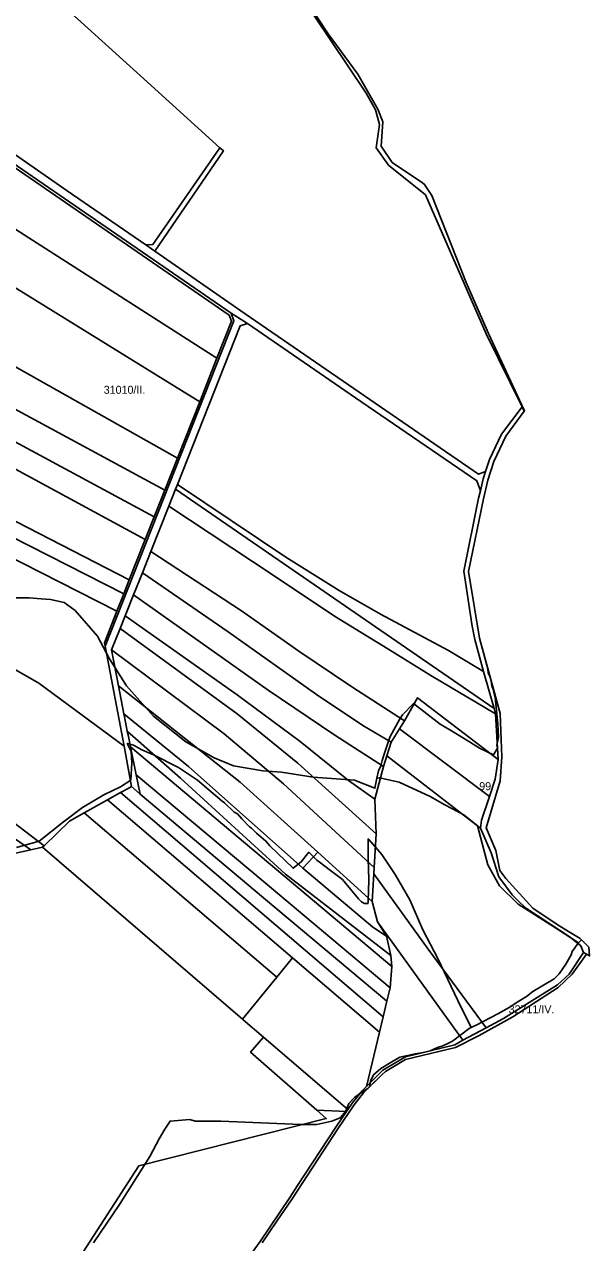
# Model space of a CAD drawing. Extents: x -541351 to -537540, y -1162694 to -1159725.
# Drawn here: x -537985 to -537632, y -1162097 to -1161336 of the extents above; entities that cross this region are included whole.
import ezdxf

# ---------------------------------------------------------------- set-up
doc = ezdxf.new("R2010")
doc.units = 0
for name, color, linetype in [('95560013', 7, 'Continuous'), ('95590013', 7, 'Continuous'), ('95600013', 7, 'Continuous'), ('95610013', 7, 'Continuous'), ('95620013', 7, 'Continuous'), ('95630013', 7, 'Continuous'), ('95640013', 7, 'Continuous'), ('95660013', 7, 'Continuous')]:
    doc.layers.add(name, color=color, linetype=linetype)

msp = doc.modelspace()

# ---------------------------------------------------------------- linework, layer by layer
at = {"layer": '95560013'}
for points in [[(-537991.61, -1161206.61), (-537962.32, -1161184.95), (-537917.43, -1161151.64), (-537878.78, -1161215.29), (-537826.79, -1161296.05), (-537771.59, -1161378.63), (-537765.56, -1161389.07), (-537763.17, -1161398.15), (-537765.32, -1161412.85), (-537757.44, -1161423.63), (-537734.41, -1161442.14), (-537710.31, -1161497.52), (-537696.57, -1161528.99), (-537674.08, -1161574.59), (-537686.87, -1161591.71), (-537694.5, -1161607.51), (-537696.89, -1161615.11), (-537701.32, -1161616.63), (-537847.19, -1161516.44), (-537903.61, -1161477.42), (-537860.67, -1161414.77), (-537862.95, -1161412.71), (-537910.48, -1161369.63), (-537986.93, -1161300.34)], [(-538017.3, -1161723.84), (-537976.1, -1161747.28), (-537922.75, -1161786.65), (-537918.1, -1161811.88), (-537920.21, -1161813.06), (-537924.94, -1161815.7), (-537933.13, -1161820.26), (-537947.8, -1161828.43), (-537956.93, -1161833.52), (-537972.84, -1161848.95), (-538003.7, -1161825.37)]]:
    msp.add_lwpolyline(points, dxfattribs=at)
for points in [[(-537862.95, -1161412.71), (-537904.74, -1161473.13), (-537909.29, -1161473.5), (-537958.26, -1161439.63), (-538014.16, -1161400.98), (-537997.12, -1161376.05), (-538023.45, -1161358.02), (-537986.93, -1161300.34), (-537910.48, -1161369.63)], [(-538105.85, -1161390.01), (-538102.7, -1161355.1), (-538068.79, -1161374.81), (-538039.72, -1161391.26), (-538023.13, -1161403.11), (-537857.1, -1161517.37), (-537855.67, -1161521.18), (-537864.8, -1161544.29)], [(-538105.85, -1161390.01), (-537864.8, -1161544.29), (-537875.53, -1161571.44), (-538109.19, -1161427.11)], [(-537860.67, -1161414.77), (-537903.61, -1161477.42), (-537909.29, -1161473.5), (-537904.74, -1161473.13), (-537862.95, -1161412.71)], [(-537875.53, -1161571.44), (-537889.5, -1161606.78), (-538114.02, -1161480.19), (-538113.05, -1161469.94), (-538110.81, -1161445.05), (-538109.19, -1161427.11)], [(-537889.5, -1161606.78), (-537897.41, -1161626.8), (-538116.68, -1161508.18), (-538114.02, -1161480.19)], [(-538116.68, -1161508.18), (-537897.41, -1161626.8), (-537903.96, -1161643.38), (-538118.52, -1161527.74), (-538118.09, -1161523)], [(-537903.96, -1161643.38), (-537909.56, -1161657.55), (-538121.06, -1161543.08), (-538120.2, -1161539.46), (-538118.52, -1161527.74)], [(-537909.56, -1161657.55), (-537919.51, -1161682.72), (-538130.97, -1161574.04), (-538129.59, -1161571.04), (-538123.99, -1161555.42), (-538121.06, -1161543.08)], [(-537919.51, -1161682.72), (-537923, -1161691.55), (-538029.12, -1161637.46), (-538135.24, -1161583.36), (-538130.97, -1161574.04)], [(-538029.12, -1161637.46), (-537923, -1161691.55), (-537927.26, -1161702.34), (-538033.98, -1161648.19), (-538140.69, -1161594.04), (-538136.53, -1161586.17), (-538135.24, -1161583.36)], [(-538171.84, -1161653.01), (-538140.69, -1161594.04), (-538033.98, -1161648.19), (-537927.26, -1161702.34), (-537935.04, -1161722.01), (-537934.61, -1161724.27), (-537922.75, -1161786.65), (-537976.1, -1161747.28), (-538017.3, -1161723.84), (-538107.66, -1161682.18)], [(-537889.44, -1161623.23), (-537821.78, -1161668.5), (-537788.35, -1161689.41), (-537762.49, -1161704.25), (-537720.04, -1161726.92), (-537698.17, -1161739.95), (-537691.59, -1161763.18), (-537890.56, -1161626.05)], [(-537837.81, -1162096.24), (-537857.15, -1162122.84), (-537876.73, -1162149.18), (-537890.98, -1162165.98), (-537913.23, -1162197.28), (-537922.33, -1162211.34), (-537935.55, -1162238.66), (-537996.43, -1162244.72), (-538003.43, -1162189.61), (-537980.73, -1162152.69), (-537959.1, -1162119.55), (-537913.59, -1162048.98), (-537796.39, -1162019.36), (-537802.31, -1162014.18), (-537783.76, -1162015.03), (-537790.37, -1162024.85), (-537814.41, -1162061.25), (-537819.11, -1162068.63)]]:
    msp.add_lwpolyline(points, close=True, dxfattribs=at)
at = {"layer": '95590013'}
for points in [[(-538091.99, -1161778.95), (-538074.06, -1161787.96), (-538055.69, -1161796.19), (-538037.67, -1161805.21), (-538020.32, -1161814.34), (-538003.7, -1161825.37), (-537972.84, -1161848.95), (-537973.7, -1161849.78), (-537981.13, -1161851.43), (-538007.24, -1161833.28), (-538024.07, -1161822.21), (-538041.78, -1161812.94), (-538059.87, -1161804.11), (-538096.14, -1161786.78), (-538132.5, -1161770.02), (-538150.71, -1161762.54), (-538201.11, -1161745.28), (-538199.78, -1161734.53), (-538146.62, -1161754.58), (-538127.98, -1161761.85), (-538109.61, -1161770.43)], [(-538026.82, -1161826.8), (-538044.18, -1161817.14), (-538062.2, -1161808.5), (-538098.22, -1161791.29), (-538135.28, -1161774.83), (-538201.84, -1161750.78), (-538201.11, -1161745.28), (-538150.71, -1161762.54), (-538132.5, -1161770.02), (-538096.14, -1161786.78), (-538059.87, -1161804.11), (-538041.78, -1161812.94), (-538024.07, -1161822.21), (-538007.24, -1161833.28), (-537981.13, -1161851.43), (-537992.56, -1161853.98), (-538010.17, -1161838.34)]]:
    msp.add_lwpolyline(points, close=True, dxfattribs=at)
at = {"layer": '95600013'}
for points in [[(-537791.3, -1161705.39), (-537829.69, -1161679.86), (-537894.84, -1161636.79), (-537890.56, -1161626.05), (-537691.59, -1161763.18), (-537690.68, -1161766.41), (-537730.97, -1161742.54), (-537758.05, -1161725.77)], [(-537849.4, -1161702.1), (-537906.05, -1161664.94), (-537894.84, -1161636.79), (-537829.69, -1161679.86), (-537791.3, -1161705.39), (-537758.05, -1161725.77), (-537730.97, -1161742.54), (-537690.68, -1161766.41), (-537688.95, -1161795.06), (-537739.44, -1161756.52), (-537747.56, -1161770.78), (-537780.43, -1161749.61), (-537813.5, -1161727.27)], [(-537780.43, -1161749.61), (-537747.56, -1161770.78), (-537750.68, -1161775.88), (-537755.79, -1161784.25), (-537773.52, -1161773.76), (-537802.6, -1161754.38), (-537857.67, -1161715.17), (-537911.36, -1161678.27), (-537906.05, -1161664.94), (-537849.4, -1161702.1), (-537813.5, -1161727.27)], [(-537857.67, -1161715.17), (-537802.6, -1161754.38), (-537773.52, -1161773.76), (-537755.79, -1161784.25), (-537758.48, -1161792.69), (-537760.6, -1161799.37), (-537791.01, -1161779.72), (-537832.83, -1161751.77), (-537916.91, -1161692.2), (-537911.36, -1161678.27)], [(-537916.91, -1161692.2), (-537832.83, -1161751.77), (-537791.01, -1161779.72), (-537760.6, -1161799.37), (-537765.99, -1161819.86), (-537782.63, -1161808.05), (-537812.67, -1161783.81), (-537852.02, -1161754.53), (-537922.07, -1161705.16)], [(-537852.02, -1161754.53), (-537812.67, -1161783.81), (-537782.63, -1161808.05), (-537765.99, -1161819.86), (-537765.19, -1161841.44), (-537814.14, -1161797.39), (-537852.09, -1161766.39), (-537925.23, -1161713.1), (-537922.07, -1161705.16)], [(-537765.19, -1161841.44), (-537766.56, -1161862.48), (-537823.19, -1161810.16), (-537860.22, -1161779.07), (-537930.6, -1161726.57), (-537925.23, -1161713.1), (-537852.09, -1161766.39), (-537814.14, -1161797.39)], [(-537801.8, -1161852.95), (-537850.3, -1161809.08), (-537926.26, -1161749.03), (-537930.6, -1161726.57), (-537860.22, -1161779.07), (-537823.19, -1161810.16), (-537766.56, -1161862.48), (-537766.78, -1161866.44), (-537767.71, -1161883.69)], [(-537850.3, -1161809.08), (-537801.8, -1161852.95), (-537811.01, -1161862.99), (-537882.54, -1161799.41), (-537922.87, -1161766.53), (-537926.26, -1161749.03)], [(-537817.45, -1161918.97), (-537763.12, -1161965.33), (-537771.22, -1161999.31), (-537773.95, -1162002.03), (-537780.15, -1162009.66), (-537782.94, -1162013.81), (-537835.7, -1161968.44), (-537848.3, -1161957.61), (-537848.8, -1161957.17), (-537827.34, -1161931.02)]]:
    msp.add_lwpolyline(points, close=True, dxfattribs=at)
at = {"layer": '95610013'}
msp.add_lwpolyline([(-537758.48, -1161792.69), (-537700.05, -1161838.01), (-537693.46, -1161853.35), (-537688.55, -1161868.27), (-537680.33, -1161879.54), (-537675.39, -1161884.28), (-537671.25, -1161888.12), (-537643.95, -1161906.13), (-537637.28, -1161911.4), (-537635.7, -1161915.56), (-537644.66, -1161929.12), (-537651.82, -1161935.75), (-537685.72, -1161956.91), (-537696.51, -1161962.69), (-537732.73, -1161913.5), (-537766.78, -1161866.44), (-537766.56, -1161862.48), (-537765.19, -1161841.44), (-537765.99, -1161819.86), (-537760.6, -1161799.37)], close=True, dxfattribs=at)
at = {"layer": '95620013'}
for points in [[(-537702.37, -1161620.84), (-537699.93, -1161627.14), (-537701.21, -1161631.77), (-537710.48, -1161677.27), (-537705.21, -1161711.74), (-537703.67, -1161719.97), (-537698.17, -1161739.95), (-537720.04, -1161726.92), (-537762.49, -1161704.25), (-537788.35, -1161689.41), (-537821.78, -1161668.5), (-537889.44, -1161623.23), (-537850.3, -1161524.02), (-537845.61, -1161522.58), (-537778.16, -1161568.95)], [(-537688.95, -1161795.06), (-537690.81, -1161807.3), (-537694.46, -1161818.19), (-537750.68, -1161775.88), (-537747.56, -1161770.78), (-537739.44, -1161756.52)], [(-537920.77, -1161777.39), (-537922.53, -1161768.3), (-537922.87, -1161766.53), (-537882.54, -1161799.41), (-537811.01, -1161862.99), (-537767.34, -1161899.85), (-537758.71, -1161905.42), (-537755.97, -1161917.48), (-537821.84, -1161866.67), (-537887.61, -1161806.63)], [(-537887.61, -1161806.63), (-537821.84, -1161866.67), (-537755.97, -1161917.48), (-537755.43, -1161924.33), (-537918.82, -1161787.06), (-537920.34, -1161779.64), (-537920.77, -1161777.39)], [(-537699.36, -1161832.85), (-537700.05, -1161838.01), (-537758.48, -1161792.69), (-537755.79, -1161784.25), (-537750.68, -1161775.88), (-537694.46, -1161818.19)], [(-537755.43, -1161924.33), (-537756.52, -1161937.62), (-537835.88, -1161871.12), (-537915.24, -1161804.63), (-537918.82, -1161787.06)], [(-537915.24, -1161804.63), (-537835.88, -1161871.12), (-537756.52, -1161937.62), (-537758.52, -1161946), (-537835.64, -1161881.39), (-537912.77, -1161816.77)], [(-537760.86, -1161955.85), (-537763.12, -1161965.33), (-537817.45, -1161918.97), (-537933.13, -1161820.26), (-537924.94, -1161815.7)], [(-537924.94, -1161815.7), (-537920.21, -1161813.06), (-537918.1, -1161811.88), (-537912.77, -1161816.77), (-537835.64, -1161881.39), (-537758.52, -1161946), (-537760.86, -1161955.85)], [(-537827.34, -1161931.02), (-537947.8, -1161828.43), (-537933.13, -1161820.26), (-537817.45, -1161918.97)], [(-537947.8, -1161828.43), (-537827.34, -1161931.02), (-537848.8, -1161957.17), (-537973.7, -1161849.78), (-537972.84, -1161848.95), (-537956.93, -1161833.52)], [(-537767.71, -1161883.69), (-537764.33, -1161896.38), (-537758.71, -1161905.42), (-537767.34, -1161899.85), (-537811.01, -1161862.99), (-537801.8, -1161852.95)], [(-537767.71, -1161883.69), (-537766.78, -1161866.44), (-537732.73, -1161913.5), (-537696.51, -1161962.69), (-537710.98, -1161970.44), (-537764.33, -1161896.38)], [(-537763.12, -1161965.33), (-537760.86, -1161955.85), (-537758.52, -1161946), (-537756.52, -1161937.62), (-537755.43, -1161924.33), (-537755.97, -1161917.48), (-537758.71, -1161905.42), (-537764.33, -1161896.38), (-537710.98, -1161970.44), (-537716.17, -1161973.22), (-537746.83, -1161980.83), (-537761.1, -1161989.21), (-537771.22, -1161999.31)], [(-537843.78, -1161977.81), (-537835.7, -1161968.44), (-537782.94, -1162013.81), (-537783.76, -1162015.03), (-537802.31, -1162014.18)]]:
    msp.add_lwpolyline(points, close=True, dxfattribs=at)
msp.add_lwpolyline([(-537992.56, -1161853.98), (-537981.13, -1161851.43), (-537973.7, -1161849.78), (-537848.8, -1161957.17), (-537848.3, -1161957.61), (-537835.7, -1161968.44), (-537843.78, -1161977.81), (-537802.31, -1162014.18), (-537796.39, -1162019.36), (-537913.59, -1162048.98), (-537959.1, -1162119.55)], dxfattribs=at)
at = {"layer": '95630013'}
msp.add_lwpolyline([(-537857.1, -1161517.37), (-538023.13, -1161403.11), (-538039.72, -1161391.26), (-538022.41, -1161401.67), (-537855.9, -1161516.2), (-537854.21, -1161520.85), (-537934.61, -1161724.27), (-537935.04, -1161722.01), (-537927.26, -1161702.34), (-537923, -1161691.55), (-537919.51, -1161682.72), (-537909.56, -1161657.55), (-537903.96, -1161643.38), (-537897.41, -1161626.8), (-537889.5, -1161606.78), (-537875.53, -1161571.44), (-537864.8, -1161544.29), (-537855.67, -1161521.18)], close=True, dxfattribs=at)
at = {"layer": '95640013'}
for points in [[(-537825.35, -1161295.54), (-537795.27, -1161341.6), (-537776.77, -1161366.86), (-537764.17, -1161388.68), (-537761.11, -1161396.65), (-537762.15, -1161411.84), (-537755.16, -1161421.95), (-537736.27, -1161434.72), (-537734.93, -1161435.64), (-537730.5, -1161442.66), (-537709.02, -1161496.84), (-537695, -1161528.73), (-537674.2, -1161573.51), (-537672.5, -1161577.12), (-537672.71, -1161577.37), (-537674.08, -1161574.59), (-537696.57, -1161528.99), (-537710.31, -1161497.52), (-537734.41, -1161442.14), (-537757.44, -1161423.63), (-537765.32, -1161412.85), (-537763.17, -1161398.15), (-537765.56, -1161389.07), (-537771.59, -1161378.63), (-537826.79, -1161296.05)], [(-537857.15, -1162122.84), (-537837.81, -1162096.24), (-537819.11, -1162068.63), (-537814.41, -1162061.25), (-537790.37, -1162024.85), (-537783.76, -1162015.03), (-537782.94, -1162013.81), (-537780.15, -1162009.66), (-537773.95, -1162002.03), (-537771.22, -1161999.31), (-537761.1, -1161989.21), (-537746.83, -1161980.83), (-537716.17, -1161973.22), (-537710.98, -1161970.44), (-537696.51, -1161962.69), (-537685.72, -1161956.91), (-537651.82, -1161935.75), (-537644.66, -1161929.12), (-537635.7, -1161915.56), (-537633.76, -1161916.66), (-537642.83, -1161929.21), (-537651.4, -1161937.54), (-537679.87, -1161955.73), (-537700.91, -1161967.52), (-537715.69, -1161974.89), (-537746.83, -1161982.53), (-537759.37, -1161989.91), (-537761.46, -1161991.89), (-537773.2, -1162003.37), (-537778.94, -1162010.74), (-537789.26, -1162025.76), (-537817.83, -1162069.52), (-537827.3, -1162083.56), (-537836.59, -1162097.02)]]:
    msp.add_lwpolyline(points, dxfattribs=at)
for points in [[(-538039.72, -1161391.26), (-538068.79, -1161374.81), (-538102.7, -1161355.1), (-538098.33, -1161347.51), (-538089.39, -1161352.67), (-538074.35, -1161361.36), (-538072.11, -1161362.66), (-538063.88, -1161366.6), (-538039.54, -1161383.43), (-538014.16, -1161400.98), (-537958.26, -1161439.63), (-537909.29, -1161473.5), (-537903.61, -1161477.42), (-537847.19, -1161516.44), (-537701.32, -1161616.63), (-537696.89, -1161615.11), (-537698.29, -1161619.58), (-537699.93, -1161627.14), (-537702.37, -1161620.84), (-537778.16, -1161568.95), (-537845.61, -1161522.58), (-537855.9, -1161516.2), (-538022.41, -1161401.67)], [(-537920.77, -1161777.39), (-537920.34, -1161779.64), (-537918.82, -1161787.06), (-537915.24, -1161804.63), (-537912.77, -1161816.77), (-537918.1, -1161811.88), (-537922.75, -1161786.65), (-537934.61, -1161724.27), (-537854.21, -1161520.85), (-537855.9, -1161516.2), (-537845.61, -1161522.58), (-537850.3, -1161524.02), (-537889.44, -1161623.23), (-537890.56, -1161626.05), (-537894.84, -1161636.79), (-537906.05, -1161664.94), (-537911.36, -1161678.27), (-537916.91, -1161692.2), (-537922.07, -1161705.16), (-537925.23, -1161713.1), (-537930.6, -1161726.57), (-537926.26, -1161749.03), (-537922.87, -1161766.53), (-537922.53, -1161768.3)], [(-537631.82, -1161917.75), (-537633.76, -1161916.66), (-537635.7, -1161915.56), (-537637.28, -1161911.4), (-537643.95, -1161906.13), (-537671.25, -1161888.12), (-537675.39, -1161884.28), (-537680.33, -1161879.54), (-537688.55, -1161868.27), (-537693.46, -1161853.35), (-537700.05, -1161838.01), (-537699.36, -1161832.85), (-537694.46, -1161818.19), (-537690.81, -1161807.3), (-537688.95, -1161795.06), (-537690.68, -1161766.41), (-537691.59, -1161763.18), (-537698.17, -1161739.95), (-537703.67, -1161719.97), (-537705.21, -1161711.74), (-537710.48, -1161677.27), (-537701.21, -1161631.77), (-537699.93, -1161627.14), (-537698.29, -1161619.58), (-537696.89, -1161615.11), (-537694.5, -1161607.51), (-537686.87, -1161591.71), (-537674.08, -1161574.59), (-537672.71, -1161577.37), (-537672.5, -1161577.12), (-537672.7, -1161577.39), (-537684.16, -1161592.93), (-537691.63, -1161608.81), (-537695.49, -1161620.49), (-537698.16, -1161632.19), (-537707.43, -1161677.5), (-537700.63, -1161719.2), (-537687.64, -1161766.24), (-537686.73, -1161793.4), (-537687.81, -1161808.36), (-537696.57, -1161837.73), (-537690.36, -1161851.82), (-537687.85, -1161864.33), (-537684.3, -1161869.41), (-537667.35, -1161887.98), (-537652.11, -1161898.02), (-537645.1, -1161902.57), (-537637.73, -1161906.76), (-537632.39, -1161912.23)]]:
    msp.add_lwpolyline(points, close=True, dxfattribs=at)
at = {"layer": '95660013'}
for points in [[(-537825.35, -1161295.54), (-537795.27, -1161341.6), (-537776.77, -1161366.86), (-537764.17, -1161388.68), (-537761.11, -1161396.65), (-537762.15, -1161411.84), (-537755.16, -1161421.95), (-537736.27, -1161434.72), (-537734.93, -1161435.64), (-537730.5, -1161442.66), (-537709.02, -1161496.84), (-537695, -1161528.73), (-537674.2, -1161573.51), (-537672.5, -1161577.12), (-537672.7, -1161577.39), (-537684.16, -1161592.93), (-537691.63, -1161608.81), (-537695.49, -1161620.49), (-537698.16, -1161632.19), (-537707.43, -1161677.5), (-537700.63, -1161719.2), (-537695.36, -1161738.27), (-537695.31, -1161741), (-537693.87, -1161744), (-537693.31, -1161746), (-537692.87, -1161749), (-537692.21, -1161751.22), (-537691.69, -1161753), (-537690.81, -1161756), (-537689.12, -1161773), (-537688.81, -1161781), (-537689.81, -1161786), (-537689.5, -1161788), (-537691.81, -1161792), (-537700.62, -1161788), (-537706.81, -1161784), (-537718.19, -1161777), (-537725.31, -1161773), (-537741.87, -1161760), (-537748.81, -1161767), (-537750.62, -1161770), (-537756.62, -1161781), (-537757.31, -1161783), (-537760.69, -1161793), (-537761.44, -1161795.67), (-537762.37, -1161799), (-537763.81, -1161802), (-537764.75, -1161806.7), (-537766, -1161813), (-537778.87, -1161808), (-537804.62, -1161806), (-537824.31, -1161803), (-537836.12, -1161802), (-537854.31, -1161799), (-537866.5, -1161794), (-537884.12, -1161784), (-537904.37, -1161768), (-537921.37, -1161749), (-537931.87, -1161732), (-537939.37, -1161718), (-537953.31, -1161702), (-537960.19, -1161697), (-537968.69, -1161695), (-537974.66, -1161694.56), (-537982.12, -1161694), (-537997.5, -1161694)], [(-537997.5, -1161694), (-537982.12, -1161694), (-537974.66, -1161694.56), (-537968.69, -1161695), (-537960.19, -1161697), (-537953.31, -1161702), (-537939.37, -1161718), (-537931.87, -1161732), (-537921.37, -1161749), (-537904.37, -1161768), (-537884.12, -1161784), (-537866.5, -1161794), (-537854.31, -1161799), (-537836.12, -1161802), (-537824.31, -1161803), (-537804.62, -1161806), (-537778.87, -1161808), (-537766, -1161813), (-537764.75, -1161806.7), (-537763.2, -1161806.4), (-537750.9, -1161809.2), (-537731.5, -1161818.1), (-537722.4, -1161823.3), (-537710.4, -1161829.6), (-537701.9, -1161836.5), (-537695.4, -1161860.8), (-537688.2, -1161874), (-537676.4, -1161885.4), (-537652.6, -1161900.6), (-537638.74, -1161909.58), (-537639.12, -1161910), (-537641.1, -1161912.78), (-537642.69, -1161915), (-537643.31, -1161917), (-537646.62, -1161923), (-537650.87, -1161929), (-537654, -1161932), (-537667.31, -1161940), (-537671.37, -1161943), (-537676, -1161946), (-537682.19, -1161950), (-537689.12, -1161954), (-537702.81, -1161961), (-537705.79, -1161962.38), (-537714.3, -1161945.7), (-537726.6, -1161919.3), (-537736.1, -1161901.4), (-537744.3, -1161882.8), (-537753.35, -1161866.86), (-537761.6, -1161854.4), (-537769.77, -1161844.97), (-537770.16, -1161844.52), (-537770.31, -1161857), (-537769.87, -1161870), (-537770.05, -1161877.22), (-537770.19, -1161883), (-537770.27, -1161883.89), (-537770.37, -1161885), (-537772.62, -1161885), (-537774.31, -1161884), (-537776.37, -1161882), (-537786.37, -1161870), (-537792.94, -1161865), (-537798.19, -1161861), (-537800.05, -1161859.67), (-537802.37, -1161858), (-537807.37, -1161853), (-537812.12, -1161859), (-537817.12, -1161863), (-537831.62, -1161849), (-537834.12, -1161846), (-537840, -1161841), (-537843.12, -1161838), (-537844.31, -1161837), (-537849.19, -1161832), (-537852, -1161829), (-537854, -1161828), (-537860, -1161822), (-537861.5, -1161821), (-537869.87, -1161814), (-537877, -1161808), (-537888.87, -1161800), (-537904.31, -1161792), (-537911.62, -1161789), (-537916.81, -1161786), (-537920.81, -1161785), (-537918.31, -1161790), (-537917.87, -1161797), (-537918.62, -1161808), (-537925.12, -1161812), (-537935.37, -1161817), (-537948.81, -1161825), (-537960.69, -1161834), (-537975.87, -1161846), (-537990.12, -1161850)], [(-537990.12, -1161850), (-537975.87, -1161846), (-537960.69, -1161834), (-537948.81, -1161825), (-537935.37, -1161817), (-537925.12, -1161812), (-537918.62, -1161808), (-537917.87, -1161797), (-537918.31, -1161790), (-537920.81, -1161785), (-537916.81, -1161786), (-537911.62, -1161789), (-537904.31, -1161792), (-537888.87, -1161800), (-537877, -1161808), (-537869.87, -1161814), (-537861.5, -1161821), (-537860, -1161822), (-537854, -1161828), (-537852, -1161829), (-537849.19, -1161832), (-537844.31, -1161837), (-537843.12, -1161838), (-537840, -1161841), (-537834.12, -1161846), (-537831.62, -1161849), (-537817.12, -1161863), (-537812.12, -1161859), (-537807.37, -1161853), (-537802.37, -1161858), (-537800.05, -1161859.67), (-537798.19, -1161861), (-537792.94, -1161865), (-537786.37, -1161870), (-537776.37, -1161882), (-537774.31, -1161884), (-537772.62, -1161885), (-537770.37, -1161885), (-537770.27, -1161883.89), (-537770.19, -1161883), (-537770.05, -1161877.22), (-537769.87, -1161870), (-537770.31, -1161857), (-537770.16, -1161844.52), (-537769.77, -1161844.97), (-537761.6, -1161854.4), (-537753.35, -1161866.86), (-537744.3, -1161882.8), (-537736.1, -1161901.4), (-537726.6, -1161919.3), (-537714.3, -1161945.7), (-537705.79, -1161962.38), (-537707.12, -1161963), (-537717.5, -1161971), (-537719.62, -1161972), (-537723.62, -1161974), (-537726.87, -1161975), (-537731.5, -1161977), (-537735.62, -1161978), (-537740.87, -1161979), (-537750.37, -1161981), (-537755.37, -1161984), (-537762.37, -1161988), (-537766.87, -1161992), (-537768.87, -1161996), (-537769.32, -1161999.58), (-537770.37, -1162000.6), (-537774.37, -1162003), (-537778.62, -1162006), (-537782.31, -1162010), (-537784.37, -1162015), (-537786.21, -1162017.22), (-537787.69, -1162019), (-537792.87, -1162021), (-537802.31, -1162023), (-537812.31, -1162023), (-537862.31, -1162021), (-537878.31, -1162021), (-537881.69, -1162020), (-537894, -1162021), (-537897.37, -1162026), (-537900.81, -1162032), (-537906.62, -1162043), (-537925.62, -1162073), (-537941.87, -1162097)], [(-537941.87, -1162097), (-537925.62, -1162073), (-537906.62, -1162043), (-537900.81, -1162032), (-537897.37, -1162026), (-537894, -1162021), (-537881.69, -1162020), (-537878.31, -1162021), (-537862.31, -1162021), (-537812.31, -1162023), (-537802.31, -1162023), (-537792.87, -1162021), (-537787.69, -1162019), (-537786.21, -1162017.22), (-537784.37, -1162015), (-537782.31, -1162010), (-537778.62, -1162006), (-537774.37, -1162003), (-537770.37, -1162000.6), (-537773.2, -1162003.37), (-537778.94, -1162010.74), (-537789.26, -1162025.76), (-537817.83, -1162069.52), (-537827.3, -1162083.56), (-537836.59, -1162097.02)]]:
    msp.add_lwpolyline(points, dxfattribs=at)
for points in [[(-537637.73, -1161906.76), (-537636.92, -1161907.59), (-537638.74, -1161909.58), (-537652.6, -1161900.6), (-537676.4, -1161885.4), (-537688.2, -1161874), (-537695.4, -1161860.8), (-537701.9, -1161836.5), (-537710.4, -1161829.6), (-537722.4, -1161823.3), (-537731.5, -1161818.1), (-537750.9, -1161809.2), (-537763.2, -1161806.4), (-537764.75, -1161806.7), (-537763.81, -1161802), (-537762.37, -1161799), (-537761.44, -1161795.67), (-537760.69, -1161793), (-537757.31, -1161783), (-537756.62, -1161781), (-537750.62, -1161770), (-537748.81, -1161767), (-537741.87, -1161760), (-537725.31, -1161773), (-537718.19, -1161777), (-537706.81, -1161784), (-537700.62, -1161788), (-537691.81, -1161792), (-537689.5, -1161788), (-537689.81, -1161786), (-537688.81, -1161781), (-537689.12, -1161773), (-537690.81, -1161756), (-537691.69, -1161753), (-537692.21, -1161751.22), (-537692.87, -1161749), (-537693.31, -1161746), (-537693.87, -1161744), (-537695.31, -1161741), (-537695.36, -1161738.27), (-537687.64, -1161766.24), (-537686.73, -1161793.4), (-537687.81, -1161808.36), (-537696.57, -1161837.73), (-537690.36, -1161851.82), (-537687.85, -1161864.33), (-537684.3, -1161869.41), (-537667.35, -1161887.98), (-537652.11, -1161898.02), (-537645.1, -1161902.57)], [(-537632.39, -1161912.23), (-537631.82, -1161917.75), (-537633.76, -1161916.66), (-537642.83, -1161929.21), (-537651.4, -1161937.54), (-537679.87, -1161955.73), (-537700.91, -1161967.52), (-537715.69, -1161974.89), (-537746.83, -1161982.53), (-537759.37, -1161989.91), (-537761.46, -1161991.89), (-537769.32, -1161999.58), (-537768.87, -1161996), (-537766.87, -1161992), (-537762.37, -1161988), (-537755.37, -1161984), (-537750.37, -1161981), (-537740.87, -1161979), (-537735.62, -1161978), (-537731.5, -1161977), (-537726.87, -1161975), (-537723.62, -1161974), (-537719.62, -1161972), (-537717.5, -1161971), (-537707.12, -1161963), (-537705.79, -1161962.38), (-537702.81, -1161961), (-537689.12, -1161954), (-537682.19, -1161950), (-537676, -1161946), (-537671.37, -1161943), (-537667.31, -1161940), (-537654, -1161932), (-537650.87, -1161929), (-537646.62, -1161923), (-537643.31, -1161917), (-537642.69, -1161915), (-537641.1, -1161912.78), (-537639.12, -1161910), (-537638.74, -1161909.58), (-537636.92, -1161907.59)]]:
    msp.add_lwpolyline(points, close=True, dxfattribs=at)

# ---------------------------------------------------------------- texts
for s, rotation, p in [('31010/II.', 0, (-537935.52, -1161566.48)), ('99', 360, (-537700.83, -1161814.18)), ('32711/IV.', 360, (-537682.46, -1161953.58))]:
    msp.add_text(s, height=5, rotation=rotation, dxfattribs=at).set_placement(p)

doc.saveas('drawing.dxf')
